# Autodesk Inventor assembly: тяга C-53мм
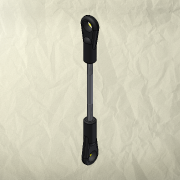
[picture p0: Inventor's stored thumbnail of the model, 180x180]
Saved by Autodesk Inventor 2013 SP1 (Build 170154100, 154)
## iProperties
Created: 2012-02
Part Number: тяга C-53мм
Document SubType Name: Assembly
Designer: WH
ipwModelExtentsX: 7.5
ipwModelExtentsY: 7.6
ipwModelExtentsZ: 60
ipwMass: N/V
ipwArea: N/V
ipwVolume: N/V
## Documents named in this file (3)
- G:\IV2k13-Forum\Rotor\Koppel C - 53mm.iam
- G:\IV2k13-Forum\Rotor\Gewindestange C.ipt
- G:\IV2k13-Forum\Rotor\Kugelpfanne 2.ipt
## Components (3 placed, 2 different names)
1. Kugelpfanne 2.ipt:1 — Passend:1, Passend:2, Winkel:1, Passend:3
2. Gewindestange C.ipt:2 — Passend:2
3. Kugelpfanne 2.ipt:3 — Passend:1, Winkel:1, Passend:3
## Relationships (4: Mate 3, Angle 1)
- Passend:1 [Mate]: Kugelpfanne 2.ipt:1 ↔ Kugelpfanne 2.ipt:3
- Passend:2 [Mate]: Kugelpfanne 2.ipt:1 ↔ Gewindestange C.ipt:2
- Winkel:1 [Angle]: Kugelpfanne 2.ipt:1 ↔ Kugelpfanne 2.ipt:3
- Passend:3 [Mate]: Kugelpfanne 2.ipt:1 ↔ Kugelpfanne 2.ipt:3
